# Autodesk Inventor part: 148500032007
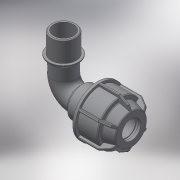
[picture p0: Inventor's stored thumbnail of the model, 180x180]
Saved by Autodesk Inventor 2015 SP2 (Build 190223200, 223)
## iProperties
Created: 2017-08
Part Number: 148500032007
Material: Generic
Description: PLASSON L. 14 90° ELBOW MALE ADAPTOR (SILVER) 32-3/4"
Document SubType Name: Modeling
Designer: KIM
Density: 1 g/cm^3
Appearance: Default
Author: KIM
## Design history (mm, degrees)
derived "148500.ipt"
feature "Solid1::148500.ipt"
feature "Solid2::148500.ipt"
tag "TaggingFeature1"
body "Solid1"
body "Solid2"
other parameters: "d1" = 32, "d2" = 56, "d4" = 15 deg, "d5" = 36.96, "d6" = 12.1968, "d10" = 61, "d16" = 32.64, "d17" = 2.8, "d22" = 51.2, "d24" = 2.8, "d25" = 54.9, "d26" = 45.75, "d27" = 2.8, "d28" = 135 deg, "d29" = 1.68, "d31" = 1.6, "d46" = 150 deg, "d49" = 3.05, "d50" = 0, "d58" = 0.96, "d61" = 360 deg, "d63" = 22.4, "d94" = 49, "d96" = 29.0851, "d97" = 18, "d98" = 21.1528, "d99" = 24.72234, "d100" = 135 deg, "d108" = 1.6, "d112" = 23.4, "d113" = 75, "d114" = 63.28, "d115" = 24.72234, "d116" = 45 deg, "d117" = 0, "d118" = 0, "d119" = 26.441, "d120" = 18, "d121" = 31.7292, "d122" = 18.9, "d123" = 1, "d_" = 32, "R_" = 26.441, "E_" = 61, "A_" = 75, "l_" = 56, "l_2" = 18, "A_1" = 49
